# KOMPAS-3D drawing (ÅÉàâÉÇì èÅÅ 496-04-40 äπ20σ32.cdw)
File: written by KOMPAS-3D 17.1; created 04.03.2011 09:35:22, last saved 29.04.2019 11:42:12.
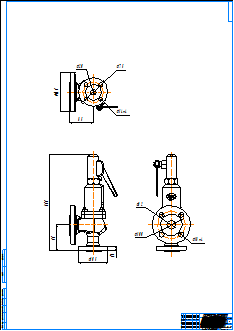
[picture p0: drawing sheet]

Sheet 1: A0, portrait

Title block, sheet 1: name: Прегран Ду 20х32; material: Внимание! Данный продукт является объектом авторского права ООО «Торговый Дом АДЛ». / Запрещается изменение, копирование, распространение / (в том числе путем копирования на другие сайты и ресурсы в Интернете) / или любое иное использование информации и объектов без предварительного / согласия правообладателя (ООО «Торговый Дом АДЛ»).; scale: 1:1; sheets: 1; organisation: ООО "Торговый дом АДЛ"; sheet format: A0; stored path: C:\Users\tra\Desktop\2д чертежи\Предохранительные клапаны ПРЕГРАН\ПРЕГРАН 496\ПРЕГРАН КПП 496-04-40\KOMPAS 2D\Прегран Ду 20х32.cdw

Views: Спереди 1, Проекционный вид 2, Проекционный вид 3
Dimensions and other numbers on the sheet: 105; 95; 350; 16; 85; 75; 14; 140; 20; 100; 18; 32; 1:1; 1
